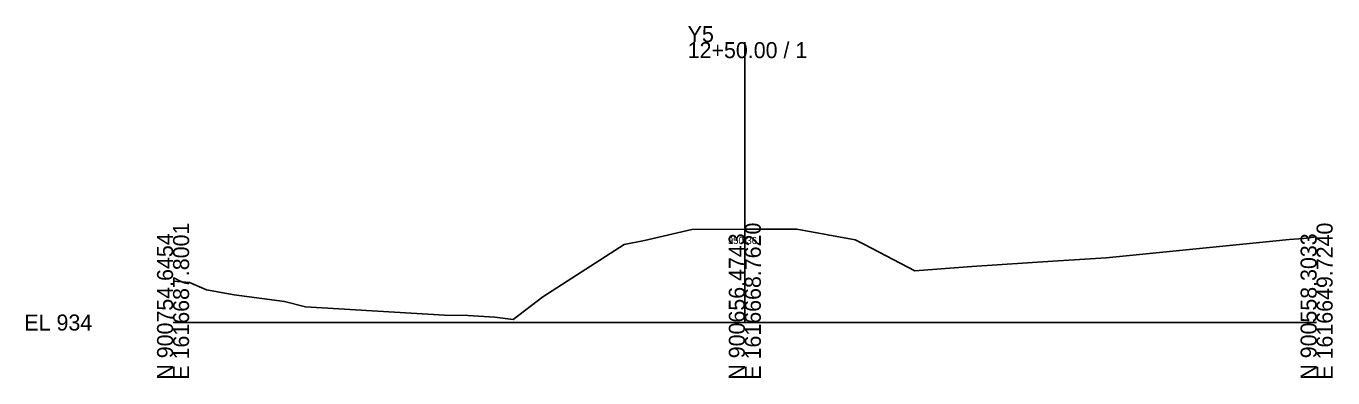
# Model space of a CAD drawing. Extents: x -26 to 1403, y -10 to 4517.
# Drawn here: x -25.7 to 202.8, y 2490.3 to 2551.9 of the extents above; entities that cross this region are included whole.
import ezdxf

# ---------------------------------------------------------------- set-up
doc = ezdxf.new("R2010")
doc.units = 0
for name, color, linetype in [('Exist Cross Section Cell', 7, 'Continuous'), ('Exist XS Center Line Elevation Label', 7, 'Continuous'), ('Exist XS Ground Line', 7, 'Continuous')]:
    doc.layers.add(name, color=color, linetype=linetype)

msp = doc.modelspace()

# ---------------------------------------------------------------- linework, layer by layer
at = {"layer": 'Exist Cross Section Cell'}
for p, q in [((100, 2500), (100, 2549.08)), ((0, 2500), (100, 2500)), ((100, 2500), (200, 2500))]:
    msp.add_line(p, q, dxfattribs=at)
at = {"layer": 'Exist XS Ground Line'}
for p, q in [((82.45, 2514.34), (90.74, 2516.28)), ((90.74, 2516.28), (99.92, 2516.36)), ((99.92, 2516.36), (109.07, 2516.34)), ((109.07, 2516.34), (119.3, 2514.46)), ((78.87, 2513.68), (82.45, 2514.34)), ((119.3, 2514.46), (120.93, 2513.68)), ((163.21, 2511.34), (192.32, 2514.26)), ((192.32, 2514.26), (195.21, 2514.52)), ((195.21, 2514.52), (197.7, 2514.69)), ((197.7, 2514.69), (200, 2515.02)), ((64.66, 2504.52), (78.87, 2513.68)), ((120.93, 2513.68), (129.72, 2509.07)), ((129.72, 2509.07), (139.68, 2509.82)), ((139.68, 2509.82), (153.89, 2510.73)), ((153.89, 2510.73), (163.21, 2511.34)), ((0, 2507.22), (2.87, 2506.99)), ((2.87, 2506.99), (5.87, 2505.73)), ((5.87, 2505.73), (10.68, 2504.82)), ((10.68, 2504.82), (19.47, 2503.65)), ((19.47, 2503.65), (23.19, 2502.74)), ((23.19, 2502.74), (47.47, 2501.29)), ((59.48, 2500.54), (64.66, 2504.52)), ((47.47, 2501.29), (51.54, 2501.21)), ((51.54, 2501.21), (56.28, 2500.96)), ((56.28, 2500.96), (59.48, 2500.54))]:
    msp.add_line(p, q, dxfattribs=at)

# ---------------------------------------------------------------- texts
at = {"layer": 'Exist Cross Section Cell'}
for s, p in [('Y5', (90, 2549.08)), ('12+50.00 / 1', (90, 2546.28)), ('EL 934', (-26, 2498.6))]:
    msp.add_text(s, height=2.8, dxfattribs=at).set_placement(p)
for s, p in [('E 1616687.8001', (2.8, 2490)), ('E 1616668.7620', (102.8, 2490)), ('E 1616649.7240', (202.8, 2490)), ('N 900754.6454', (0, 2490)), ('N 900656.4743', (100, 2490)), ('N 900558.3033', (200, 2490))]:
    msp.add_text(s, height=2.8, rotation=90, dxfattribs=at).set_placement(p)
at = {"layer": 'Exist XS Center Line Elevation Label'}
msp.add_text('950.36', height=1.25, dxfattribs=at).set_placement((97.02, 2513.74))

doc.saveas('drawing.dxf')
